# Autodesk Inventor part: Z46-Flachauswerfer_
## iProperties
Company: HASCO
k: 3,000 mm
d1: 4,200 mm
d2: 8,000 mm
r: 0,300 mm
l2: 30,000 mm
d36: 30,000 mm
d0: 30,000 mm
b: 0,800 mm
a: 3,800 mm
l1: 60,000 mm
Author: Claus Cordt
Shininess: 20.0
Angle Display Precision: 2
Document Length Units: 11269
Document Angle Units: 11283
Document Time Units: 11279
Document Mass Units: 11290
Document Length Units Precision: 3
Document Angle Units Precision: 2
Compacted: False
PropertySet Name: _Private Model Information
Created: 2002-08
Part Number: Z46-Flachauswerfer_
Material: Stahl (schweißbar)
Document SubType Name: Modellieren
Designer: Claus Cordt
Control State: 0
Master: False
Checked Out: False
PropertySet Name: Design Tracking Control
Density: 0.0
Volumn: 0.0
Area: 0.0
PropertySet Name: Model Information
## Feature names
1. Drehung1 [Revolution]
2. Rundung1 [Fillet]
3. Extrusion5
4. Extrusion6
5. Extrusion7
